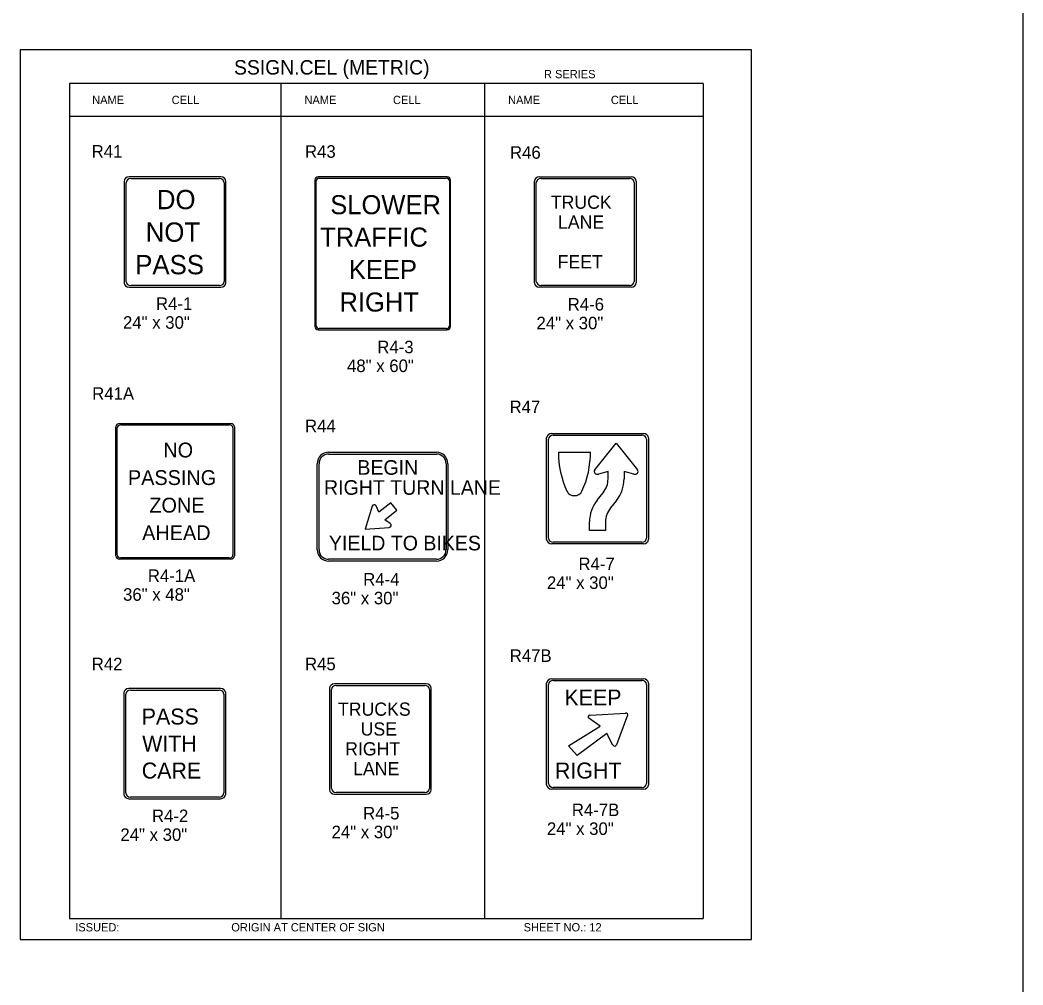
# Model space of a CAD drawing. Extents: x -5299 to 22597, y -19549 to -1808.
# Drawn here: x -1179 to -218, y -4576 to -3652 of the extents above; entities that cross this region are included whole.
import ezdxf

# ---------------------------------------------------------------- set-up
doc = ezdxf.new("R2010")
doc.units = 0
for name, color, linetype in [('Level 1', 7, 'Continuous'), ('Level 2', 7, 'Continuous'), ('Level 3', 7, 'Continuous'), ('Level 63', 7, 'Continuous')]:
    doc.layers.add(name, color=color, linetype=linetype)

msp = doc.modelspace()

# ---------------------------------------------------------------- linework, layer by layer
at = {"layer": 'Level 1'}
for p, q in [((-524.67, -3712.28), (-1131.69, -3712.28)), ((-1131.69, -3712.28), (-1131.69, -4512.28)), ((-929.35, -3712.28), (-929.35, -4512.28)), ((-734.22, -3712.28), (-734.22, -4512.28)), ((-524.67, -3712.28), (-524.67, -4512.28)), ((-524.67, -3743.95), (-1131.69, -3743.95)), ((-1073.11, -3803.5), (-988.22, -3803.5)), ((-892.46, -3803.06), (-770.85, -3803.06)), ((-679.98, -3803.37), (-595.09, -3803.37)), ((-1077.62, -3902.12), (-1077.62, -3807.41)), ((-983.71, -3807.41), (-983.71, -3902.12)), ((-895.47, -3944.48), (-895.47, -3805.77)), ((-767.84, -3805.77), (-767.84, -3944.48)), ((-684.49, -3901.98), (-684.49, -3807.28)), ((-590.58, -3807.28), (-590.58, -3901.98)), ((-1030.66, -3854.76), (-1030.66, -3854.76)), ((-637.53, -3854.63), (-637.53, -3854.63)), ((-831.65, -3875.12), (-831.65, -3875.12)), ((-988.22, -3906.03), (-1073.11, -3906.03)), ((-595.09, -3905.89), (-679.98, -3905.89)), ((-770.85, -3947.18), (-892.46, -3947.18)), ((-1086.15, -4163.98), (-1086.15, -4042.37)), ((-1082.64, -4039.36), (-978.68, -4039.36)), ((-975.17, -4042.37), (-975.17, -4163.98)), ((-672.78, -4147.96), (-672.78, -4053.25)), ((-668.26, -4049.34), (-583.38, -4049.34)), ((-578.87, -4053.25), (-578.87, -4147.96)), ((-628.51, -4082.58), (-608.07, -4056.89)), ((-608.07, -4056.89), (-587.55, -4082.58)), ((-883.49, -4067.41), (-780.17, -4067.41)), ((-663.31, -4065.61), (-632.57, -4065.61)), ((-892.73, -4158.97), (-892.73, -4076.65)), ((-770.93, -4076.65), (-770.93, -4158.97)), ((-615.72, -4084.27), (-624.92, -4086.71)), ((-615.72, -4091.24), (-615.72, -4084.27)), ((-591.14, -4086.71), (-600.35, -4084.27)), ((-600.35, -4084.27), (-600.35, -4091.24)), ((-1030.66, -4103.18), (-1030.66, -4103.18)), ((-625.82, -4100.6), (-625.82, -4100.6)), ((-626.09, -4111.52), (-620.48, -4104.49)), ((-607.76, -4112), (-613.38, -4119.03)), ((-831.83, -4117.81), (-831.83, -4117.81)), ((-633.51, -4140.6), (-633.51, -4132.28)), ((-618.13, -4132.28), (-618.13, -4140.6)), ((-618.13, -4140.6), (-633.51, -4140.6)), ((-583.38, -4151.86), (-668.26, -4151.86)), ((-978.68, -4166.99), (-1082.64, -4166.99)), ((-780.17, -4168.21), (-883.49, -4168.21)), ((-668.26, -4284.3), (-583.38, -4284.3)), ((-1073.38, -4293.5), (-988.49, -4293.5)), ((-880.84, -4387.68), (-880.84, -4292.97)), ((-876.33, -4289.06), (-791.44, -4289.06)), ((-786.93, -4292.97), (-786.93, -4387.68)), ((-672.78, -4382.92), (-672.78, -4288.21)), ((-578.87, -4288.21), (-578.87, -4382.92)), ((-1077.89, -4392.11), (-1077.89, -4297.4)), ((-983.98, -4297.4), (-983.98, -4392.11)), ((-623.21, -4328.19), (-634.13, -4320.48)), ((-633.04, -4317.64), (-598.87, -4315.61)), ((-596.99, -4317.64), (-607.61, -4346.04)), ((-653.8, -4346.98), (-623.21, -4328.19)), ((-833.88, -4340.32), (-833.88, -4340.32)), ((-616.97, -4335.08), (-645.37, -4356.18)), ((-625.82, -4335.56), (-625.82, -4335.56)), ((-611.04, -4346.17), (-616.97, -4335.08)), ((-1030.94, -4344.76), (-1030.94, -4344.76)), ((-645.37, -4356.18), (-653.8, -4346.98)), ((-791.44, -4391.59), (-876.33, -4391.59)), ((-583.38, -4386.82), (-668.26, -4386.82)), ((-988.49, -4396.02), (-1073.38, -4396.02)), ((-1131.69, -4512.28), (-524.67, -4512.28))]:
    msp.add_line(p, q, dxfattribs=at)
for points in [[(-841.85, -4117.48), (-848.35, -4139.52), (-825.43, -4137.63)], [(-824.48, -4133.85), (-829.65, -4130.49), (-818.11, -4121.25), (-823.99, -4114.11), (-835.53, -4123.14), (-838.06, -4117.05), (-838.06, -4117.05)]]:
    msp.add_lwpolyline(points, dxfattribs=at)
for centre, radius, start, end in [((-883.49, -4076.65), 9.24, 90, 180), ((-780.17, -4076.65), 9.24, 0, 90), ((-839.88, -4117.95), 2.03, 26.31931, 166.57119), ((-825.63, -4135.57), 2.08, 275.55756, 56.09935), ((-883.49, -4158.97), 9.24, 180, 270), ((-780.17, -4158.97), 9.24, 270, 0)]:
    msp.add_arc(centre, radius, start, end, dxfattribs=at)
for centre, major_axis, ratio, start_param, end_param in [((-1073.11, -3807.41), (-4.51, 0), 0.866667, 4.712389, 6.283185), ((-988.22, -3807.41), (-4.51, 0), 0.866667, 3.141593, 4.712389), ((-892.46, -3805.77), (-3.01, 0), 0.9, 4.712389, 6.283185), ((-770.85, -3805.77), (-3.01, 0), 0.9, 3.141593, 4.712389), ((-679.98, -3807.28), (-4.51, 0), 0.866667, 4.712389, 6.283185), ((-595.09, -3807.28), (-4.51, 0), 0.866667, 3.141593, 4.712389), ((-1073.11, -3902.12), (4.51, 0), 0.866667, 3.141593, 4.712389), ((-988.22, -3902.12), (4.51, 0), 0.866667, 4.712389, 6.283185), ((-679.98, -3901.98), (4.51, 0), 0.866667, 3.141593, 4.712389), ((-595.09, -3901.98), (4.51, 0), 0.866667, 4.712389, 6.283185), ((-892.46, -3944.48), (3.01, 0), 0.9, 3.141593, 4.712389), ((-770.85, -3944.48), (3.01, 0), 0.9, 4.712389, 6.283185), ((-1082.64, -4042.37), (-3.51, 0), 0.857082, 4.712389, 6.283185), ((-978.68, -4042.37), (-3.51, 0), 0.857082, 3.141593, 4.712389), ((-668.27, -4053.25), (-4.51, 0), 0.866667, 4.712389, 6.283185), ((-583.38, -4053.25), (-4.51, 0), 0.866667, 3.141593, 4.712389), ((-548.28, -4066.03), (115.05, 0), 0.866667, 3.137591, 3.522165), ((-748.05, -4065.96), (-115.48, 0), 0.866667, 2.761745, 3.144869), ((-625.86, -4084.06), (3.2, 0), 0.866667, 2.568526, 5.001662), ((-590.26, -4084.06), (-3.2, 0), 0.866667, 1.281523, 3.71466), ((-642.63, -4091.25), (26.88, 0), 0.866667, 5.679854, 6.283438), ((-642.86, -4091.22), (42.49, 0), 0.866667, 5.684484, 6.282418), ((-647.95, -4100.62), (7.68, 0), 0.866667, 3.517117, 5.907661), ((-591.24, -4132.28), (-42.29, 0), 0.866667, 5.680583, 6.283185), ((-591.38, -4132.26), (26.77, 0), 0.866667, 2.533053, 3.14213), ((-668.27, -4147.96), (4.51, 0), 0.866667, 3.141593, 4.712389), ((-583.38, -4147.96), (4.51, 0), 0.866667, 4.712389, 6.283185), ((-1082.64, -4163.98), (3.51, 0), 0.857082, 3.141593, 4.712389), ((-978.68, -4163.98), (3.51, 0), 0.857082, 4.712389, 6.283185), ((-668.27, -4288.21), (-4.51, 0), 0.866667, 4.712389, 6.283185), ((-583.38, -4288.21), (-4.51, 0), 0.866667, 3.141593, 4.712389), ((-1073.38, -4297.41), (-4.51, 0), 0.866667, 4.712389, 6.283185), ((-988.49, -4297.41), (-4.51, 0), 0.866667, 3.141593, 4.712389), ((-876.33, -4292.97), (-4.51, 0), 0.866667, 4.712389, 6.283185), ((-791.44, -4292.97), (-4.51, 0), 0.866667, 3.141593, 4.712389), ((-633.02, -4319.23), (1.88, 0), 0.866667, 1.619302, 4.048856), ((-598.74, -4317.17), (-1.89, 0), 0.866667, 2.836574, 4.787444), ((-609.34, -4345.5), (1.88, 0), 0.866667, 3.559508, 5.980834), ((-876.33, -4387.68), (4.51, 0), 0.866667, 3.141593, 4.712389), ((-791.44, -4387.68), (4.51, 0), 0.866667, 4.712389, 6.283185), ((-668.27, -4382.92), (4.51, 0), 0.866667, 3.141593, 4.712389), ((-583.38, -4382.92), (4.51, 0), 0.866667, 4.712389, 6.283185), ((-1073.38, -4392.11), (4.51, 0), 0.866667, 3.141593, 4.712389), ((-988.49, -4392.11), (4.51, 0), 0.866667, 4.712389, 6.283185)]:
    msp.add_ellipse(centre, major_axis=major_axis, ratio=ratio, start_param=start_param, end_param=end_param, dxfattribs=at)
at = {"layer": 'Level 3'}
for p, q in [((-218.2, -1877.72), (-218.2, -9425.73)), ((-986.77, -3801.93), (-1074.55, -3801.93)), ((-896.68, -3804.9), (-896.68, -3945.35)), ((-769.88, -3801.97), (-893.43, -3801.97)), ((-766.63, -3945.35), (-766.63, -3804.9)), ((-681.42, -3801.8), (-593.64, -3801.8)), ((-1079.43, -3806.16), (-1079.43, -3903.37)), ((-981.9, -3903.37), (-981.9, -3806.16)), ((-686.3, -3903.23), (-686.3, -3806.03)), ((-588.77, -3806.03), (-588.77, -3903.23)), ((-1074.55, -3907.59), (-986.77, -3907.59)), ((-593.64, -3907.46), (-681.42, -3907.46)), ((-893.43, -3948.27), (-769.88, -3948.27)), ((-1087.56, -4164.95), (-1087.56, -4041.41)), ((-1083.77, -4038.16), (-977.56, -4038.16)), ((-973.77, -4041.41), (-973.77, -4164.95)), ((-674.59, -4149.21), (-674.59, -4052)), ((-669.71, -4047.77), (-581.93, -4047.77)), ((-577.06, -4052), (-577.06, -4149.21)), ((-883.49, -4065.73), (-780.17, -4065.73)), ((-894.41, -4158.97), (-894.41, -4076.65)), ((-769.25, -4076.65), (-769.25, -4158.97)), ((-581.93, -4153.43), (-669.71, -4153.43)), ((-977.56, -4168.2), (-1083.77, -4168.2)), ((-780.17, -4169.89), (-883.49, -4169.89)), ((-669.71, -4282.73), (-581.93, -4282.73)), ((-987.05, -4291.93), (-1074.83, -4291.93)), ((-882.65, -4291.72), (-882.65, -4388.93)), ((-789.99, -4287.49), (-877.77, -4287.49)), ((-785.12, -4388.93), (-785.12, -4291.72)), ((-674.59, -4384.17), (-674.59, -4286.96)), ((-577.06, -4286.96), (-577.06, -4384.17)), ((-1079.7, -4296.15), (-1079.7, -4393.36)), ((-982.17, -4393.36), (-982.17, -4296.15)), ((-581.93, -4388.39), (-669.71, -4388.39)), ((-1074.83, -4397.59), (-987.05, -4397.59)), ((-877.77, -4393.15), (-789.99, -4393.15))]:
    msp.add_line(p, q, dxfattribs=at)
for centre, start, end in [((-883.49, -4076.65), 90, 180), ((-780.17, -4076.65), 0, 90), ((-883.49, -4158.97), 180, 270), ((-780.17, -4158.97), 270, 0)]:
    msp.add_arc(centre, 10.92, start, end, dxfattribs=at)
for centre, major_axis, ratio, start_param, end_param in [((-1074.55, -3806.16), (-4.88, 0), 0.866667, 4.712389, 6.283185), ((-986.77, -3806.16), (-4.88, 0), 0.866667, 3.141593, 4.712389), ((-893.43, -3804.9), (-3.25, 0), 0.9, 4.712389, 6.283185), ((-769.89, -3804.9), (-3.25, 0), 0.9, 3.141593, 4.712389), ((-681.42, -3806.03), (-4.88, 0), 0.866667, 4.712389, 6.283185), ((-593.65, -3806.03), (-4.88, 0), 0.866667, 3.141593, 4.712389), ((-1074.55, -3903.37), (4.88, 0), 0.866667, 3.141593, 4.712389), ((-986.77, -3903.37), (4.88, 0), 0.866667, 4.712389, 6.283185), ((-681.42, -3903.23), (4.88, 0), 0.866667, 3.141593, 4.712389), ((-593.65, -3903.23), (4.88, 0), 0.866667, 4.712389, 6.283185), ((-893.43, -3945.35), (3.25, 0), 0.9, 3.141593, 4.712389), ((-769.89, -3945.35), (3.25, 0), 0.9, 4.712389, 6.283185), ((-1083.77, -4041.41), (-3.79, 0), 0.857082, 4.712389, 6.283185), ((-977.56, -4041.41), (-3.79, 0), 0.857082, 3.141593, 4.712389), ((-669.71, -4052), (-4.88, 0), 0.866667, 4.712389, 6.283185), ((-581.93, -4052), (-4.88, 0), 0.866667, 3.141593, 4.712389), ((-669.71, -4149.21), (4.88, 0), 0.866667, 3.141593, 4.712389), ((-581.93, -4149.21), (4.88, 0), 0.866667, 4.712389, 6.283185), ((-1083.77, -4164.95), (3.79, 0), 0.857082, 3.141593, 4.712389), ((-977.56, -4164.95), (3.79, 0), 0.857082, 4.712389, 6.283185), ((-669.71, -4286.96), (-4.88, 0), 0.866667, 4.712389, 6.283185), ((-581.93, -4286.96), (-4.88, 0), 0.866667, 3.141593, 4.712389), ((-1074.83, -4296.15), (-4.88, 0), 0.866667, 4.712389, 6.283185), ((-987.05, -4296.15), (-4.88, 0), 0.866667, 3.141593, 4.712389), ((-877.77, -4291.72), (-4.88, 0), 0.866667, 4.712389, 6.283185), ((-789.99, -4291.72), (-4.88, 0), 0.866667, 3.141593, 4.712389), ((-877.77, -4388.93), (4.88, 0), 0.866667, 3.141593, 4.712389), ((-789.99, -4388.93), (4.88, 0), 0.866667, 4.712389, 6.283185), ((-669.71, -4384.17), (4.88, 0), 0.866667, 3.141593, 4.712389), ((-581.93, -4384.17), (4.88, 0), 0.866667, 4.712389, 6.283185), ((-1074.83, -4393.36), (4.88, 0), 0.866667, 3.141593, 4.712389), ((-987.05, -4393.36), (4.88, 0), 0.866667, 4.712389, 6.283185)]:
    msp.add_ellipse(centre, major_axis=major_axis, ratio=ratio, start_param=start_param, end_param=end_param, dxfattribs=at)
at = {"layer": 'Level 63'}
msp.add_lwpolyline([(-1179.2, -4532.47), (-478.15, -4532.47), (-478.15, -3680.09), (-1179.2, -3680.09)], close=True, dxfattribs=at)

# ---------------------------------------------------------------- texts
at = {"layer": 'Level 1'}
for s, height, p in [('DO', 18.49, (-1048.13, -3832.84)), ('SLOWER', 18.287, (-881.93, -3837.63)), ('TRUCK', 12.679, (-670.65, -3832.44)), ('LANE', 12.679, (-663.74, -3851.46)), ('NOT', 18.49, (-1058.8, -3864.01)), ('TRAFFIC', 18.287, (-891.61, -3868.72)), ('PASS', 18.49, (-1068.88, -3895.18)), ('KEEP', 18.287, (-864.09, -3899.81)), ('FEET', 12.679, (-664.09, -3889.5)), ('RIGHT', 18.287, (-873.13, -3930.9)), ('NO', 14.223, (-1041.92, -4070.66)), ('BEGIN', 14, (-855.96, -4087.25)), ('PASSING', 14.223, (-1075.81, -4097.08)), ('RIGHT TURN LANE', 14, (-887.93, -4106.46)), ('ZONE', 14.223, (-1055.29, -4123.49)), ('AHEAD', 14.223, (-1062.17, -4149.91)), ('YIELD TO BIKES', 14, (-883.23, -4159.69)), ('KEEP', 15.321, (-657.56, -4308.31)), ('TRUCKS', 12.679, (-874.6, -4318.14)), ('PASS', 15.321, (-1062.6, -4326.53)), ('USE', 12.679, (-852.83, -4337.15)), ('WITH', 15.321, (-1062.18, -4352.42)), ('RIGHT', 12.679, (-867.69, -4356.17)), ('CARE', 15.321, (-1062.6, -4378.3)), ('LANE', 12.679, (-860.09, -4375.19)), ('RIGHT', 15.321, (-666.67, -4378.28))]:
    msp.add_text(s, height=height, dxfattribs=at).set_placement(p)
at = {"layer": 'Level 2'}
for s, p in [('R41', (-1110.59, -3783.41)), ('R43', (-906.15, -3783.52)), ('R46', (-709.71, -3784.45)), ('R41A', (-1110.06, -4015.45)), ('R47', (-710.12, -4028.2)), ('R44', (-906.15, -4046.48)), ('R47B', (-709.96, -4266.55)), ('R42', (-1110.49, -4274.57)), ('R45', (-906.15, -4274.55))]:
    msp.add_text(s, height=12, dxfattribs=at).set_placement(p)
at = {"layer": 'Level 3'}
for s, height, p in [('SSIGN.CEL (METRIC)', 13.8566, (-974.16, -3703.84)), ('R SERIES', 7.918, (-677.17, -3707.33)), ('NAME', 7.918, (-1110.1, -3732.11)), ('CELL', 7.918, (-1033.96, -3732.11)), ('NAME', 7.918, (-906.65, -3732.11)), ('CELL', 7.918, (-821.88, -3732.11)), ('NAME', 7.918, (-711.56, -3732.11)), ('CELL', 7.918, (-613.06, -3732.11)), ('R4-1', 12, (-1048.94, -3929.34)), ('R4-6', 12, (-654.44, -3929.91)), ('24" x 30"', 12, (-1080.54, -3947.34)), ('24" x 30"', 12, (-684.35, -3947.91)), ('R4-3', 12, (-836.9, -3970.84)), ('48" x 60"', 12, (-865.88, -3988.84)), ('R4-7', 12, (-644.11, -4178.6)), ('R4-1A', 12, (-1056.78, -4189.95)), ('R4-4', 12, (-850.41, -4193.39)), ('24" x 30"', 12, (-674.35, -4196.6)), ('36" x 48"', 12, (-1080.5, -4207.95)), ('36" x 30"', 12, (-880.65, -4211.39)), ('R4-2', 12, (-1052.8, -4420.03)), ('R4-5', 12, (-850.46, -4417.47)), ('R4-7B', 12, (-650.44, -4414.29)), ('24" x 30"', 12, (-674.35, -4432.29)), ('24" x 30"', 12, (-1083.04, -4438.03)), ('24" x 30"', 12, (-880.69, -4435.47)), ('ISSUED:', 7.918, (-1126.33, -4524.77)), ('ORIGIN AT CENTER OF SIGN', 7.9181, (-976.79, -4524.77)), ('SHEET NO.: 12', 7.918, (-696.63, -4524.77))]:
    msp.add_text(s, height=height, dxfattribs=at).set_placement(p)

doc.saveas('drawing.dxf')
